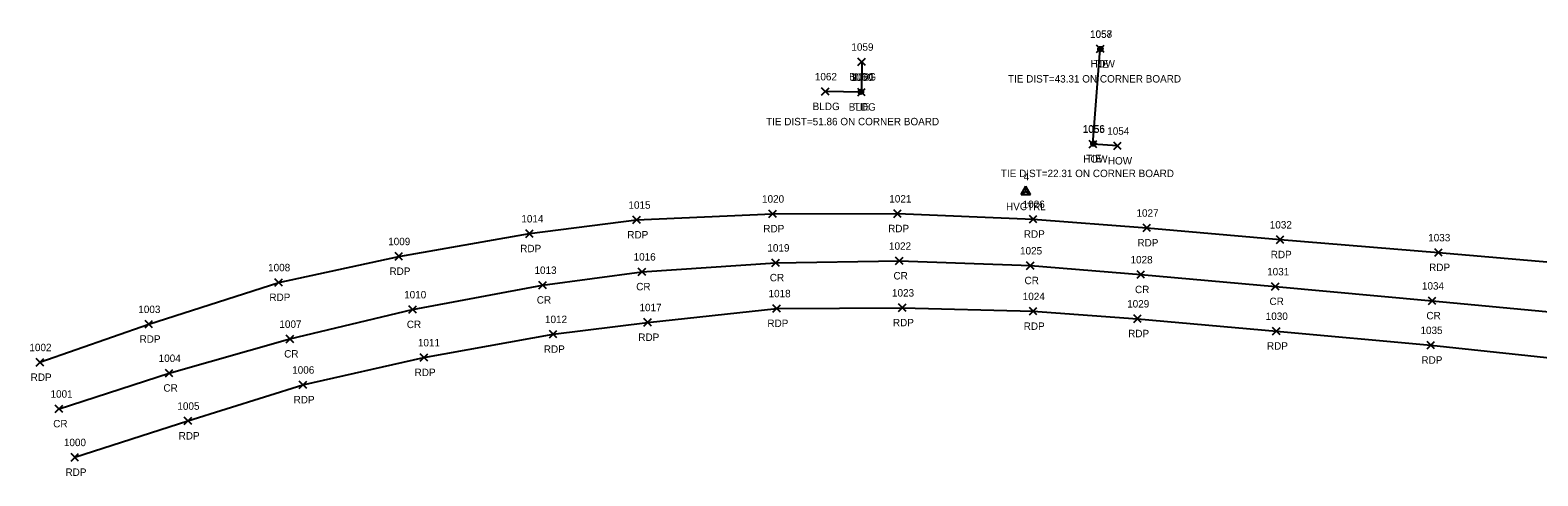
# Model space of a CAD drawing. Extents: x 1657482 to 1661439, y 647981 to 649041.
# Drawn here: x 1659288.8 to 1659694.6, y 648063.4 to 648183.4 of the extents above; entities that cross this region are included whole.
import ezdxf

# ---------------------------------------------------------------- set-up
doc = ezdxf.new("R2010")
doc.units = 0
for name, color, linetype in [('C_A', 7, 'Continuous'), ('C_C', 7, 'Continuous'), ('C_I', 7, 'Continuous'), ('CBP', 7, 'Continuous'), ('CPSM', 7, 'Continuous'), ('L_A', 7, 'Continuous'), ('L_I', 7, 'Continuous'), ('L_TIC', 7, 'Continuous'), ('LBC', 7, 'Continuous'), ('P_A', 7, 'Continuous'), ('P_I', 7, 'Continuous'), ('P_TIC', 7, 'Continuous'), ('PET', 7, 'Continuous'), ('PRC', 7, 'Continuous')]:
    doc.layers.add(name, color=color, linetype=linetype)

msp = doc.modelspace()

# ---------------------------------------------------------------- linework, layer by layer
at = {"layer": 'CBP'}
for centre, radius in [((1659576.84, 648178.28), 0.625), ((1659576.84, 648178.28), 0.0833), ((1659512.39, 648166.77), 0.625), ((1659512.39, 648166.77), 0.0833), ((1659574.94, 648152.82), 0.625), ((1659574.94, 648152.82), 0.0833)]:
    msp.add_circle(centre, radius, dxfattribs=at)
at = {"layer": 'CPSM'}
for p, q in [((1659555.5, 648139.18), (1659556.75, 648141.35)), ((1659558, 648139.18), (1659556.75, 648141.35)), ((1659556.75, 648139.91), (1659556.75, 648141.35)), ((1659555.5, 648139.18), (1659556.75, 648139.91)), ((1659555.5, 648139.18), (1659558, 648139.18)), ((1659556.75, 648139.91), (1659556.75, 648139.91)), ((1659556.75, 648139.91), (1659558, 648139.18))]:
    msp.add_line(p, q, dxfattribs=at)
at = {"layer": 'L_TIC'}
for points in [[(1659575.81, 648177.35), (1659577.81, 648179.35)], [(1659577.81, 648177.35), (1659575.81, 648179.35)], [(1659511.59, 648173.84), (1659513.59, 648175.84)], [(1659513.59, 648173.84), (1659511.59, 648175.84)], [(1659501.8, 648165.86), (1659503.8, 648167.86)], [(1659503.8, 648165.86), (1659501.8, 648167.86)], [(1659511.51, 648165.7), (1659513.51, 648167.7)], [(1659513.51, 648165.7), (1659511.51, 648167.7)], [(1659573.84, 648151.7), (1659575.84, 648153.7)], [(1659575.84, 648151.7), (1659573.84, 648153.7)], [(1659580.44, 648151.22), (1659582.44, 648153.22)], [(1659582.44, 648151.22), (1659580.44, 648153.22)]]:
    msp.add_lwpolyline(points, dxfattribs=at)
at = {"layer": 'LBC'}
for points in [[(1659581.44, 648152.22), (1659574.84, 648152.7), (1659576.81, 648178.35)], [(1659512.59, 648174.84), (1659512.51, 648166.7), (1659502.8, 648166.86)]]:
    msp.add_lwpolyline(points, dxfattribs=at)
at = {"layer": 'P_TIC'}
for points in [[(1659451.01, 648131.3), (1659453.01, 648133.3)], [(1659453.01, 648131.3), (1659451.01, 648133.3)], [(1659487.62, 648132.94), (1659489.62, 648134.94)], [(1659489.62, 648132.94), (1659487.62, 648134.94)], [(1659521.21, 648132.98), (1659523.21, 648134.98)], [(1659523.21, 648132.98), (1659521.21, 648134.98)], [(1659557.73, 648131.5), (1659559.73, 648133.5)], [(1659559.73, 648131.5), (1659557.73, 648133.5)], [(1659422.18, 648127.6), (1659424.18, 648129.6)], [(1659424.18, 648127.6), (1659422.18, 648129.6)], [(1659588.31, 648129.15), (1659590.31, 648131.15)], [(1659590.31, 648129.15), (1659588.31, 648131.15)], [(1659624.19, 648125.98), (1659626.19, 648127.98)], [(1659626.19, 648125.98), (1659624.19, 648127.98)], [(1659386.99, 648121.49), (1659388.99, 648123.49)], [(1659388.99, 648121.49), (1659386.99, 648123.49)], [(1659488.42, 648119.77), (1659490.42, 648121.77)], [(1659490.42, 648119.77), (1659488.42, 648121.77)], [(1659521.71, 648120.26), (1659523.71, 648122.26)], [(1659523.71, 648120.26), (1659521.71, 648122.26)], [(1659556.98, 648118.99), (1659558.98, 648120.99)], [(1659558.98, 648118.99), (1659556.98, 648120.99)], [(1659666.83, 648122.52), (1659668.83, 648124.52)], [(1659668.83, 648122.52), (1659666.83, 648124.52)], [(1659452.45, 648117.35), (1659454.45, 648119.35)], [(1659454.45, 648117.35), (1659452.45, 648119.35)], [(1659586.71, 648116.58), (1659588.71, 648118.58)], [(1659588.71, 648116.58), (1659586.71, 648118.58)], [(1659354.67, 648114.47), (1659356.67, 648116.47)], [(1659356.67, 648114.47), (1659354.67, 648116.47)], [(1659425.71, 648113.76), (1659427.71, 648115.76)], [(1659427.71, 648113.76), (1659425.71, 648115.76)], [(1659622.92, 648113.37), (1659624.92, 648115.37)], [(1659624.92, 648113.37), (1659622.92, 648115.37)], [(1659390.72, 648107.17), (1659392.72, 648109.17)], [(1659392.72, 648107.17), (1659390.72, 648109.17)], [(1659488.71, 648107.47), (1659490.71, 648109.47)], [(1659490.71, 648107.47), (1659488.71, 648109.47)], [(1659522.51, 648107.66), (1659524.51, 648109.66)], [(1659524.51, 648107.66), (1659522.51, 648109.66)], [(1659557.71, 648106.7), (1659559.71, 648108.7)], [(1659559.71, 648106.7), (1659557.71, 648108.7)], [(1659665.14, 648109.53), (1659667.14, 648111.53)], [(1659667.14, 648109.53), (1659665.14, 648111.53)], [(1659319.73, 648103.22), (1659321.73, 648105.22)], [(1659321.73, 648103.22), (1659319.73, 648105.22)], [(1659453.97, 648103.72), (1659455.97, 648105.72)], [(1659455.97, 648103.72), (1659453.97, 648105.72)], [(1659585.81, 648104.71), (1659587.81, 648106.71)], [(1659587.81, 648104.71), (1659585.81, 648106.71)], [(1659357.71, 648099.24), (1659359.71, 648101.24)], [(1659359.71, 648099.24), (1659357.71, 648101.24)], [(1659428.54, 648100.52), (1659430.54, 648102.52)], [(1659430.54, 648100.52), (1659428.54, 648102.52)], [(1659623.19, 648101.37), (1659625.19, 648103.37)], [(1659625.19, 648101.37), (1659623.19, 648103.37)], [(1659664.75, 648097.57), (1659666.75, 648099.57)], [(1659666.75, 648097.57), (1659664.75, 648099.57)], [(1659290.42, 648092.96), (1659292.42, 648094.96)], [(1659292.42, 648092.96), (1659290.42, 648094.96)], [(1659393.77, 648094.25), (1659395.77, 648096.25)], [(1659395.77, 648094.25), (1659393.77, 648096.25)], [(1659325.21, 648090.06), (1659327.21, 648092.06)], [(1659327.21, 648090.06), (1659325.21, 648092.06)], [(1659361.2, 648086.9), (1659363.2, 648088.9)], [(1659363.2, 648086.9), (1659361.2, 648088.9)], [(1659295.54, 648080.44), (1659297.54, 648082.44)], [(1659297.54, 648080.44), (1659295.54, 648082.44)], [(1659330.25, 648077.18), (1659332.25, 648079.18)], [(1659332.25, 648077.18), (1659330.25, 648079.18)], [(1659299.79, 648067.39), (1659301.79, 648069.39)], [(1659301.79, 648067.39), (1659299.79, 648069.39)]]:
    msp.add_lwpolyline(points, dxfattribs=at)
at = {"layer": 'PET'}
for points in [[(1659291.42, 648093.96), (1659320.73, 648104.22), (1659355.67, 648115.47), (1659387.99, 648122.49), (1659423.18, 648128.6), (1659452.01, 648132.3), (1659488.62, 648133.94), (1659522.21, 648133.98), (1659558.73, 648132.5), (1659589.31, 648130.15), (1659625.19, 648126.98), (1659667.83, 648123.52), (1659700.15, 648120.78)], [(1659300.79, 648068.39), (1659331.25, 648078.18), (1659362.2, 648087.9), (1659394.77, 648095.25), (1659429.54, 648101.52), (1659454.97, 648104.72), (1659489.71, 648108.47), (1659523.51, 648108.66), (1659558.71, 648107.7), (1659586.81, 648105.71), (1659624.19, 648102.37), (1659665.75, 648098.57), (1659698.63, 648095.12)]]:
    msp.add_lwpolyline(points, dxfattribs=at)
at = {"layer": 'PRC'}
msp.add_lwpolyline([(1659296.54, 648081.44), (1659326.21, 648091.06), (1659358.71, 648100.24), (1659391.72, 648108.17), (1659426.71, 648114.76), (1659453.45, 648118.35), (1659489.42, 648120.77), (1659522.71, 648121.26), (1659557.98, 648119.99), (1659587.71, 648117.58), (1659623.92, 648114.37), (1659666.14, 648110.53), (1659699.55, 648107.38)], dxfattribs=at)

# ---------------------------------------------------------------- texts
at = {"layer": 'C_A'}
for s, p in [('TIE', (1659574.92, 648173.28)), ('TIE', (1659510.47, 648161.77)), ('TIE', (1659573.02, 648147.82)), ('HVCTRL', (1659551.44, 648134.91))]:
    msp.add_text(s, height=2, dxfattribs=at).set_placement(p)
at = {"layer": 'C_C'}
for s, p in [('TIE DIST=43.31 ON CORNER BOARD', (1659551.95, 648169.28)), ('TIE DIST=51.86 ON CORNER BOARD', (1659486.84, 648157.77)), ('TIE DIST=22.31 ON CORNER BOARD', (1659550.05, 648143.82))]:
    msp.add_text(s, height=2, dxfattribs=at).set_placement(p)
at = {"layer": 'C_I'}
for s, p in [('1057', (1659574.06, 648181.28)), ('1061', (1659510.14, 648169.77)), ('1056', (1659572.11, 648155.82)), ('4', (1659556.18, 648142.91))]:
    msp.add_text(s, height=2, dxfattribs=at).set_placement(p)
at = {"layer": 'L_A'}
for s, p in [('HOW', (1659574.2, 648173.35)), ('BLDG', (1659509.18, 648169.84)), ('BLDG', (1659499.39, 648161.86)), ('BLDG', (1659509.1, 648161.7)), ('HOW', (1659572.23, 648147.7)), ('HOW', (1659578.83, 648147.22))]:
    msp.add_text(s, height=2, dxfattribs=at).set_placement(p)
at = {"layer": 'L_I'}
for s, p in [('1058', (1659574.04, 648181.35)), ('1059', (1659509.81, 648177.84)), ('1062', (1659499.98, 648169.86)), ('1060', (1659509.61, 648169.7)), ('1055', (1659572.07, 648155.7)), ('1054', (1659578.67, 648155.22))]:
    msp.add_text(s, height=2, dxfattribs=at).set_placement(p)
at = {"layer": 'P_A'}
for s, p in [('RDP', (1659449.5, 648127.3)), ('RDP', (1659486.11, 648128.94)), ('RDP', (1659519.7, 648128.98)), ('RDP', (1659556.22, 648127.5)), ('RDP', (1659420.67, 648123.6)), ('RDP', (1659586.8, 648125.15)), ('RDP', (1659622.68, 648121.98)), ('RDP', (1659385.48, 648117.49)), ('CR', (1659487.85, 648115.77)), ('CR', (1659521.14, 648116.26)), ('CR', (1659556.41, 648114.99)), ('RDP', (1659665.31, 648118.52)), ('CR', (1659451.89, 648113.35)), ('CR', (1659586.14, 648112.58)), ('RDP', (1659353.16, 648110.47)), ('CR', (1659425.14, 648109.76)), ('CR', (1659622.35, 648109.37)), ('CR', (1659390.15, 648103.17)), ('RDP', (1659487.2, 648103.47)), ('RDP', (1659520.99, 648103.66)), ('RDP', (1659556.19, 648102.7)), ('CR', (1659664.58, 648105.53)), ('RDP', (1659318.22, 648099.22)), ('RDP', (1659452.46, 648099.72)), ('RDP', (1659584.3, 648100.71)), ('CR', (1659357.14, 648095.24)), ('RDP', (1659427.03, 648096.52)), ('RDP', (1659621.67, 648097.37)), ('RDP', (1659663.24, 648093.57)), ('RDP', (1659288.91, 648088.96)), ('RDP', (1659392.26, 648090.25)), ('CR', (1659324.64, 648086.06)), ('RDP', (1659359.69, 648082.9)), ('CR', (1659294.98, 648076.44)), ('RDP', (1659328.74, 648073.18)), ('RDP', (1659298.28, 648063.39))]:
    msp.add_text(s, height=2, dxfattribs=at).set_placement(p)
at = {"layer": 'P_I'}
for s, p in [('1015', (1659449.8, 648135.3)), ('1020', (1659485.76, 648136.94)), ('1021', (1659520.01, 648136.98)), ('1026', (1659555.91, 648135.5)), ('1014', (1659420.98, 648131.6)), ('1027', (1659586.54, 648133.15)), ('1032', (1659622.42, 648129.98)), ('1009', (1659385.13, 648125.49)), ('1019', (1659487.2, 648123.77)), ('1022', (1659519.93, 648124.26)), ('1025', (1659555.2, 648122.99)), ('1033', (1659665.06, 648126.52)), ('1016', (1659451.19, 648121.35)), ('1028', (1659584.94, 648120.58)), ('1008', (1659352.82, 648118.47)), ('1013', (1659424.51, 648117.76)), ('1031', (1659621.71, 648117.37)), ('1010', (1659389.43, 648111.17)), ('1018', (1659487.51, 648111.47)), ('1023', (1659520.74, 648111.66)), ('1024', (1659555.93, 648110.7)), ('1034', (1659663.37, 648113.53)), ('1003', (1659317.88, 648107.22)), ('1017', (1659452.77, 648107.72)), ('1029', (1659584.03, 648108.71)), ('1007', (1659355.86, 648103.24)), ('1012', (1659427.34, 648104.52)), ('1030', (1659621.33, 648105.37)), ('1035', (1659662.98, 648101.57)), ('1002', (1659288.57, 648096.96)), ('1011', (1659393.13, 648098.25)), ('1004', (1659323.36, 648094.06)), ('1006', (1659359.3, 648090.9)), ('1001', (1659294.26, 648084.44)), ('1005', (1659328.4, 648081.18)), ('1000', (1659297.85, 648071.39))]:
    msp.add_text(s, height=2, dxfattribs=at).set_placement(p)

doc.saveas('drawing.dxf')
